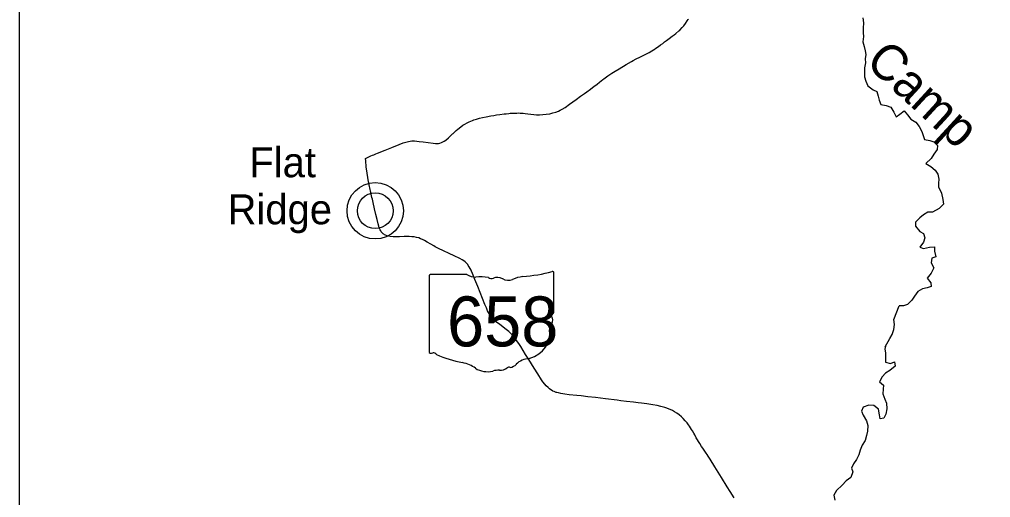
# Model space of a CAD drawing. Extents: x -12.1 to 34, y 0 to 22.
# Drawn here: x -12.146 to -9.741, y 16.219 to 17.402 of the extents above; entities that cross this region are included whole.
import ezdxf

# ---------------------------------------------------------------- set-up
doc = ezdxf.new("R2010")
doc.units = 0
for name, color, linetype in [('GM_X_Minor_River', 7, 'Continuous'), ('GM_X_Minor_River_Text', 7, 'Continuous'), ('GM_X_State_Route', 7, 'Continuous'), ('GM_X_State_Shield', 7, 'Continuous'), ('GM_X_Unincorporated', 7, 'Continuous'), ('GM_X_Unincorporated_Location', 7, 'Continuous'), ('GM_X_Unincorporated_Text', 7, 'Continuous'), ('SH_Text', 7, 'Continuous')]:
    doc.layers.add(name, color=color, linetype=linetype)

msp = doc.modelspace()

# ---------------------------------------------------------------- linework, layer by layer
at = {"layer": 'GM_X_Minor_River'}
for points in [[(-10.0569, 17.4059), (-10.0557, 17.3935), (-10.0563, 17.38), (-10.0562, 17.369), (-10.0554, 17.3594), (-10.0571, 17.3462), (-10.0538, 17.3349), (-10.0512, 17.3243), (-10.0497, 17.315), (-10.0513, 17.3044), (-10.0505, 17.2948), (-10.0533, 17.2823), (-10.0528, 17.2709), (-10.0531, 17.2603), (-10.0501, 17.2489), (-10.045, 17.238), (-10.0318, 17.2281), (-10.0226, 17.224)], [(-10.0226, 17.224), (-10.0196, 17.2119), (-10.0171, 17.2023), (-10.0124, 17.1917), (-9.9996, 17.189), (-9.9879, 17.1852), (-9.9803, 17.1728), (-9.9749, 17.1612), (-9.9654, 17.1673), (-9.9552, 17.1759), (-9.9469, 17.1657), (-9.938, 17.1555), (-9.9259, 17.1481), (-9.9176, 17.1369), (-9.9111, 17.1245), (-9.9075, 17.1149), (-9.9042, 17.105), (-9.891, 17.1026), (-9.8811, 17.0995), (-9.8725, 17.09), (-9.8728, 17.0804), (-9.8812, 17.069), (-9.8881, 17.0582), (-9.9008, 17.0457), (-9.889, 17.038), (-9.8783, 17.0292), (-9.8718, 17.019), (-9.8692, 17.0065), (-9.8695, 16.9969), (-9.8694, 16.9877), (-9.8622, 16.9725), (-9.8588, 16.9562), (-9.8577, 16.9452), (-9.8678, 16.9341), (-9.8847, 16.9254), (-9.8964, 16.9253), (-9.9066, 16.9184), (-9.9158, 16.9112), (-9.9267, 16.9004), (-9.9266, 16.8908), (-9.9158, 16.8771), (-9.9069, 16.8726), (-9.9033, 16.8619), (-9.9071, 16.8509), (-9.9162, 16.8387), (-9.9066, 16.8356), (-9.8921, 16.8382), (-9.8793, 16.8391), (-9.8796, 16.8288), (-9.8762, 16.8149), (-9.8865, 16.8109), (-9.8882, 16.7999), (-9.8813, 16.7875), (-9.8879, 16.7739), (-9.8977, 16.7621), (-9.8887, 16.7505), (-9.8883, 16.7409), (-9.8975, 16.738), (-9.9091, 16.735), (-9.9208, 16.7292), (-9.9292, 16.717), (-9.9362, 16.7077), (-9.9467, 16.6963), (-9.9566, 16.6937), (-9.9668, 16.6932)], [(-10.0015, 16.5918), (-9.9905, 16.6127), (-9.9846, 16.6227), (-9.9805, 16.6344), (-9.9788, 16.6469), (-9.9807, 16.6593), (-9.9668, 16.6932)], [(-10.0004, 16.5971), (-10.0025, 16.5865), (-10.0013, 16.5772), (-10.0012, 16.5644), (-10.0008, 16.5541), (-9.9887, 16.5504), (-9.9791, 16.5551), (-9.9772, 16.5437), (-9.9906, 16.5336), (-10.0009, 16.5268), (-10.0093, 16.5178), (-10.0163, 16.5057), (-10.0059, 16.4969), (-10.0065, 16.4869), (-10.0078, 16.4752), (-10.0024, 16.4621), (-9.9984, 16.4522), (-9.9979, 16.4387), (-10.0006, 16.4252), (-10.0048, 16.4155), (-10.0144, 16.414), (-10.0159, 16.4233), (-10.0185, 16.4374), (-10.0303, 16.4469), (-10.0427, 16.4479), (-10.0565, 16.4424), (-10.0607, 16.4328), (-10.0567, 16.4232), (-10.0484, 16.4087), (-10.0451, 16.3974), (-10.046, 16.3832), (-10.0477, 16.3725), (-10.0515, 16.3604), (-10.0588, 16.3482), (-10.0637, 16.3365), (-10.0675, 16.3247), (-10.073, 16.3133), (-10.08, 16.3025), (-10.0849, 16.2915), (-10.0816, 16.2823), (-10.0872, 16.2684), (-10.0988, 16.2604), (-10.1083, 16.2493), (-10.1227, 16.2368), (-10.129, 16.2246), (-10.1268, 16.2129)]]:
    msp.add_lwpolyline(points, dxfattribs=at)
at = {"layer": 'GM_X_State_Route'}
msp.add_lwpolyline([(-10.3758, 16.2181), (-10.3856, 16.2338), (-10.393, 16.2456), (-10.407, 16.2682), (-10.4235, 16.2946), (-10.4356, 16.3139), (-10.4404, 16.3212), (-10.4429, 16.3251), (-10.4455, 16.3291), (-10.4536, 16.3412), (-10.4565, 16.3455), (-10.4613, 16.3529), (-10.4697, 16.3665), (-10.4737, 16.374), (-10.4761, 16.3783), (-10.4792, 16.3839), (-10.4815, 16.3875), (-10.4839, 16.3913), (-10.4869, 16.3958), (-10.4892, 16.399), (-10.4927, 16.4035), (-10.4971, 16.4089), (-10.502, 16.4144), (-10.5066, 16.4188), (-10.512, 16.4234), (-10.5176, 16.4275), (-10.5238, 16.4314), (-10.529, 16.4342), (-10.5341, 16.4366), (-10.5367, 16.4378), (-10.5424, 16.44), (-10.548, 16.4419), (-10.5507, 16.4428), (-10.5573, 16.4445), (-10.5665, 16.4466), (-10.577, 16.4485), (-10.5919, 16.4509), (-10.6057, 16.4525), (-10.6138, 16.4535), (-10.6249, 16.4549), (-10.6428, 16.457), (-10.6567, 16.4586), (-10.6659, 16.4597), (-10.6943, 16.4634), (-10.7197, 16.4664), (-10.7381, 16.4685), (-10.7546, 16.4703), (-10.766, 16.4714), (-10.7845, 16.4733), (-10.7955, 16.4748), (-10.8053, 16.4764), (-10.8111, 16.4777), (-10.8149, 16.4787), (-10.8166, 16.4792), (-10.82, 16.4804), (-10.8214, 16.481), (-10.8248, 16.4826), (-10.8261, 16.4833), (-10.8298, 16.4854), (-10.833, 16.4879), (-10.8367, 16.4909), (-10.8412, 16.4952), (-10.8451, 16.4996), (-10.8495, 16.5052), (-10.8528, 16.51), (-10.8623, 16.5247), (-10.8716, 16.5395), (-10.8843, 16.5604), (-10.8924, 16.5732), (-10.9045, 16.5924), (-10.908, 16.5978), (-10.9115, 16.6031), (-10.9172, 16.6112), (-10.9221, 16.6176), (-10.9255, 16.6215), (-10.9291, 16.6252), (-10.9343, 16.6299), (-10.9407, 16.6351), (-10.9563, 16.6469), (-10.9643, 16.6533), (-10.9693, 16.6579), (-10.9735, 16.662), (-10.977, 16.666), (-10.9793, 16.6692), (-10.9801, 16.6703), (-10.9809, 16.6715), (-10.9829, 16.6745), (-10.9841, 16.6765), (-10.9865, 16.6809), (-10.9897, 16.688), (-10.9934, 16.697), (-11.0109, 16.7408), (-11.0181, 16.7586), (-11.0239, 16.7732), (-11.0264, 16.779), (-11.0276, 16.7817), (-11.0297, 16.7858), (-11.0323, 16.7902), (-11.0346, 16.7935), (-11.0359, 16.7952), (-11.0391, 16.7988), (-11.0425, 16.8019), (-11.0457, 16.8044), (-11.0497, 16.807), (-11.0556, 16.8103), (-11.0691, 16.8169), (-11.0818, 16.8227), (-11.096, 16.8295), (-11.1081, 16.8354), (-11.1163, 16.8397), (-11.1199, 16.8417), (-11.1276, 16.8459), (-11.1362, 16.8509), (-11.1427, 16.8547), (-11.1482, 16.8576), (-11.1525, 16.8594), (-11.1572, 16.8612), (-11.1629, 16.8627), (-11.1686, 16.8638), (-11.1741, 16.8644), (-11.1807, 16.8647), (-11.1934, 16.8646), (-11.2045, 16.864), (-11.2146, 16.8637), (-11.2209, 16.8638), (-11.2283, 16.8646), (-11.2325, 16.8655), (-11.2354, 16.8663), (-11.2393, 16.8679), (-11.2422, 16.8694), (-11.2438, 16.8703), (-11.2454, 16.8716), (-11.2471, 16.873), (-11.2491, 16.8752), (-11.2502, 16.8767), (-11.2515, 16.8786), (-11.2531, 16.8813), (-11.2543, 16.8843), (-11.2552, 16.8866), (-11.2564, 16.8904), (-11.258, 16.8966), (-11.2603, 16.9071), (-11.2631, 16.9195), (-11.2665, 16.9337), (-11.2702, 16.9492), (-11.2721, 16.9571), (-11.2731, 16.961), (-11.276, 16.9737), (-11.2784, 16.9851), (-11.2791, 16.9885), (-11.2822, 17.0051), (-11.2858, 17.0271), (-11.2871, 17.0363), (-11.2878, 17.0416), (-11.2883, 17.0477), (-11.2886, 17.0519), (-11.289, 17.058), (-11.279, 17.0625), (-11.2756, 17.0642), (-11.2714, 17.0662), (-11.2687, 17.0673), (-11.2671, 17.0679), (-11.2632, 17.0692), (-11.259, 17.0711), (-11.2401, 17.0787), (-11.2238, 17.085), (-11.2055, 17.0925), (-11.1957, 17.0963), (-11.189, 17.0985), (-11.1827, 17.1002), (-11.1787, 17.1009), (-11.1745, 17.1013), (-11.1675, 17.1013), (-11.1564, 17.1003), (-11.146, 17.0991), (-11.1218, 17.0957), (-11.1161, 17.0952), (-11.1121, 17.0952), (-11.1081, 17.0954), (-11.1048, 17.0961), (-11.101, 17.0973), (-11.0974, 17.0989), (-11.094, 17.1009), (-11.0903, 17.1036), (-11.0836, 17.1092), (-11.0733, 17.1186), (-11.0716, 17.1201), (-11.0678, 17.1237), (-11.0643, 17.1269), (-11.0603, 17.1303), (-11.0527, 17.1366), (-11.0479, 17.14), (-11.0429, 17.1431), (-11.0372, 17.1462), (-11.032, 17.1488), (-11.0239, 17.1523), (-11.0206, 17.1535), (-11.0173, 17.1547), (-11.0145, 17.1555), (-11.0071, 17.1574), (-10.9992, 17.1591), (-10.9906, 17.1609), (-10.9786, 17.1633), (-10.9716, 17.1645), (-10.9643, 17.1657), (-10.9562, 17.1668), (-10.9453, 17.1681), (-10.9407, 17.1686), (-10.9338, 17.1694), (-10.9309, 17.1697), (-10.9263, 17.1699), (-10.9216, 17.1702), (-10.9146, 17.1704), (-10.9112, 17.1706), (-10.9059, 17.1704), (-10.9018, 17.1701), (-10.8989, 17.1698), (-10.8938, 17.1691), (-10.8868, 17.1682), (-10.8794, 17.1673), (-10.8719, 17.1665), (-10.8655, 17.1661), (-10.858, 17.166), (-10.8499, 17.1665), (-10.8419, 17.1674), (-10.8327, 17.1688), (-10.8248, 17.1705), (-10.8175, 17.1725), (-10.8111, 17.1749), (-10.8065, 17.1772), (-10.8019, 17.1798), (-10.7946, 17.1844), (-10.7837, 17.1921), (-10.7672, 17.2041), (-10.7563, 17.2119), (-10.7463, 17.219), (-10.7412, 17.2227), (-10.7317, 17.2296), (-10.7224, 17.2366), (-10.7164, 17.2412), (-10.7151, 17.2422), (-10.7096, 17.2465), (-10.7013, 17.253), (-10.6986, 17.2551), (-10.6888, 17.2625), (-10.684, 17.2658), (-10.6791, 17.269), (-10.6707, 17.2741), (-10.6611, 17.2797), (-10.6431, 17.2902), (-10.6305, 17.2975), (-10.626, 17.3), (-10.6183, 17.3041), (-10.6099, 17.3083), (-10.5965, 17.3152), (-10.5867, 17.3204), (-10.5796, 17.3243), (-10.5718, 17.3293), (-10.5698, 17.3306), (-10.5631, 17.335), (-10.558, 17.3388), (-10.5528, 17.3426), (-10.5483, 17.3462), (-10.5435, 17.3496), (-10.537, 17.3545), (-10.5291, 17.3604), (-10.5249, 17.3635), (-10.5203, 17.3671), (-10.5128, 17.3734), (-10.5102, 17.3757), (-10.5046, 17.3816), (-10.5008, 17.3859), (-10.4967, 17.3915), (-10.492, 17.3981), (-10.4898, 17.4015), (-10.4892, 17.4025)], dxfattribs=at)
at = {"layer": 'GM_X_State_Shield'}
for p, q in [((-11.1317, 16.7673), (-11.1317, 16.5797)), ((-11.0382, 16.7706), (-11.1287, 16.7706)), ((-10.8227, 16.6771), (-10.8227, 16.7752)), ((-10.8227, 16.6771), (-10.8227, 16.6771))]:
    msp.add_line(p, q, dxfattribs=at)
for centre, major_axis, start_param, end_param in [((-11.1282, 16.7677), (0.00358, 0), 1.712693, 3.28349), ((-11.0166, 16.7924), (0.0347, 0), 4.042523, 4.731795), ((-10.9328, 17.0264), (0.3277, 0), 4.814394, 5.042369), ((-10.8261, 16.7756), (0.00344, 0), 6.141152, 7.989035), ((-11.0051, 16.6652), (0.1246, 0), 1.404758, 1.657858), ((-10.9768, 16.7687), (0.01, 0), 3.836095, 5.185415), ((-10.9621, 16.747), (0.0208, 0), 0.950623, 2.079405), ((-10.9352, 16.7768), (0.0251, 0), 4.081561, 5.145723), ((-10.891, 16.7133), (0.0659, 0), 1.699011, 2.107814), ((-10.8235, 16.6699), (0.00532, 0), 1.883978, 3.671073), ((-10.8264, 16.6767), (0.00368, 0), 5.05454, 6.418171), ((-10.8104, 16.636), (0.0232, 0), 2.387724, 3.262537), ((-10.8574, 16.6575), (0.032, 0), 5.934695, 6.695948), ((-10.9144, 16.6235), (0.082, 0), 5.101752, 6.440018), ((-11.1281, 16.5793), (0.00361, 0), 3.00124, 4.508301), ((-11.1276, 16.5985), (0.0276, 0), 4.665946, 4.897461), ((-11.1219, 16.5689), (0.00994, 0), 0.519207, 1.627899), ((-10.9965, 16.7375), (0.2366, 0), 4.195997, 4.488961), ((-11.067, 16.4954), (0.074, 0), 0.823519, 1.323587), ((-10.8799, 16.5271), (0.0449, 0), 1.647645, 2.488434), ((-10.987, 16.568), (0.047, 0), 4.026481, 4.996735), ((-10.9598, 16.5031), (0.0386, 0), 1.495662, 1.94098), ((-10.9564, 16.5539), (0.025, 0), 4.691044, 5.507374), ((-10.9337, 16.5358), (0.00705, 0), 1.147584, 2.315152), ((-10.9367, 16.5615), (0.0265, 0), 4.937069, 5.64225)]:
    msp.add_ellipse(centre, major_axis=major_axis, ratio=0.8, start_param=start_param, end_param=end_param, dxfattribs=at)
at = {"layer": 'GM_X_Unincorporated'}
for radius in [0.0698, 0.0442]:
    msp.add_circle((-11.2649, 16.9286), radius, dxfattribs=at)
at = {"layer": 'GM_X_Unincorporated_Location'}
msp.add_line((-11.2649, 16.9286), (-11.2649, 16.9286), dxfattribs=at)
at = {"layer": 'SH_Text'}
msp.add_lwpolyline([(-12.1463, 20.3063), (-4.4383, 20.3063), (-4.4383, 10.9773), (-12.1463, 10.9773)], close=True, dxfattribs=at)

# ---------------------------------------------------------------- texts
at = {"layer": 'GM_X_Minor_River_Text'}
msp.add_text('Camp', height=0.08877, rotation=317.3793, dxfattribs=at).set_placement((-10.0542, 17.2926))
at = {"layer": 'GM_X_State_Shield'}
msp.add_text('658', height=0.1236, dxfattribs=at).set_placement((-11.0871, 16.593))
at = {"layer": 'GM_X_Unincorporated_Text'}
for s, p in [('Flat', (-11.5768, 17.0115)), ('Ridge', (-11.6307, 16.8951))]:
    msp.add_text(s, height=0.07404, rotation=0, dxfattribs=at).set_placement(p)

doc.saveas('drawing.dxf')
